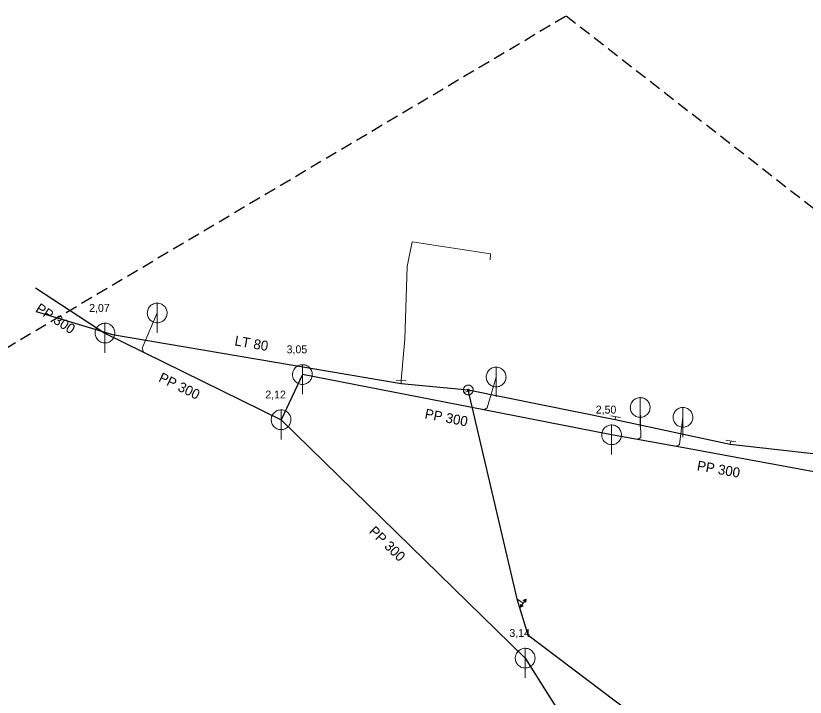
# Model space of a CAD drawing. Extents: x -683466 to -682479, y -996772 to -995963.
# Drawn here: x -683391.7 to -683311.7, y -996032.3 to -995963.2 of the extents above; entities that cross this region are included whole.
import ezdxf

# ---------------------------------------------------------------- set-up
doc = ezdxf.new("R2010")
doc.units = 0
doc.header["$LTSCALE"] = 0.4
doc.linetypes.add('MEDIUM_DASHED', pattern=[4.5, 3, -1.5])
doc.layers.add('1', color=7, linetype='Continuous')
for name, color, linetype, lineweight in [('11', 7, 'Continuous', 13), ('13', 7, 'Continuous', 13), ('14', 7, 'Continuous', 25), ('17', 7, 'Continuous', 25), ('22', 7, 'Continuous', 13), ('34', 7, 'Continuous', 13), ('47', 7, 'Continuous', 13), ('63', 7, 'MEDIUM_DASHED', 25)]:
    doc.layers.add(name, color=color, linetype=linetype, lineweight=lineweight)

msp = doc.modelspace()

# ---------------------------------------------------------------- linework, layer by layer
at = {"layer": '11'}
for points in [[(-683377.379, -995993.34), (-683378.896, -995996.921), (-683378.767, -995997.3)], [(-683343.05, -995999.829), (-683343.965, -996002.943), (-683344.296, -996003.166)], [(-683328.46, -996002.92), (-683328.388, -996005.949), (-683328.719, -996006.171)], [(-683324.129, -996003.91), (-683324.464, -996006.666), (-683324.795, -996006.888)]]:
    msp.add_lwpolyline(points, dxfattribs=at)
at = {"layer": '13'}
msp.add_lwpolyline([(-683352.66, -996000.18), (-683352.3, -995995.96), (-683352.059, -995988.629), (-683351.539, -995986.12), (-683343.629, -995987.34), (-683343.638, -995987.967)], dxfattribs=at)
at = {"layer": '14'}
for p, q in [((-683389.719, -995990.809), (-683382.67, -995995.379)), ((-683364.829, -996004.16), (-683340.109, -996028.32)), ((-683340.109, -996028.32), (-683325.27, -996051.789))]:
    msp.add_line(p, q, dxfattribs=at)
at = {"layer": '14', "lineweight": 13}
for p, q in [((-683352.66, -996000.18), (-683352.676, -996000.479)), ((-683345.871, -996001.145), (-683345.87, -996001.27)), ((-683330.998, -996004.133), (-683330.949, -996003.85)), ((-683319.329, -996006.62), (-683319.28, -996006.32))]:
    msp.add_line(p, q, dxfattribs=at)
at = {"layer": '14'}
for points in [[(-683382.67, -995995.379), (-683378.767, -995997.3), (-683364.829, -996004.16)], [(-683331.359, -996005.69), (-683344.296, -996003.166), (-683362.67, -995999.579), (-683364.829, -996004.16)], [(-683307.55, -996010.039), (-683324.795, -996006.888), (-683328.719, -996006.171), (-683331.359, -996005.69)]]:
    msp.add_lwpolyline(points, dxfattribs=at)
at = {"layer": '17'}
for points in [[(-683389.647, -995993.19), (-683381.916, -995995.522), (-683352.676, -996000.479), (-683345.871, -996001.145)], [(-683345.871, -996001.145), (-683330.998, -996004.133), (-683319.329, -996006.62), (-683296.567, -996009.217), (-683292.577, -996009.418), (-683277.891, -996009.01), (-683274.249, -996009.008), (-683238.954, -996008.579)], [(-683345.87, -996001.27), (-683340.96, -996022.3), (-683339.832, -996025.943), (-683304.056, -996053.017), (-683282.79, -996067.766), (-683274.905, -996069.189), (-683269.5, -996070.27), (-683248.91, -996070.167), (-683229.542, -996070.96), (-683219.888, -996069.96)]]:
    msp.add_lwpolyline(points, dxfattribs=at)
at = {"layer": '22'}
for p, q in [((-683377.379, -995995.34), (-683377.378, -995992.34)), ((-683382.67, -995997.379), (-683382.669, -995994.379)), ((-683362.67, -996001.579), (-683362.669, -995998.579)), ((-683343.05, -996001.829), (-683343.049, -995998.829)), ((-683328.46, -996004.92), (-683328.459, -996001.92)), ((-683364.829, -996006.16), (-683364.828, -996003.16)), ((-683324.129, -996005.91), (-683324.128, -996002.91)), ((-683331.359, -996007.69), (-683331.358, -996004.69)), ((-683340.109, -996030.32), (-683340.108, -996027.32))]:
    msp.add_line(p, q, dxfattribs=at)
for points in [[(-683376.379, -995993.34), (-683376.384, -995993.231), (-683376.402, -995993.123), (-683376.432, -995993.017), (-683376.472, -995992.916), (-683376.524, -995992.819), (-683376.586, -995992.729), (-683376.658, -995992.646), (-683376.738, -995992.572), (-683376.826, -995992.506), (-683376.92, -995992.451), (-683377.02, -995992.406), (-683377.125, -995992.373), (-683377.232, -995992.351), (-683377.341, -995992.341), (-683377.451, -995992.343), (-683377.559, -995992.357), (-683377.666, -995992.382), (-683377.769, -995992.419), (-683377.867, -995992.468), (-683377.959, -995992.526), (-683378.045, -995992.595), (-683378.122, -995992.672), (-683378.191, -995992.758), (-683378.25, -995992.85), (-683378.298, -995992.948), (-683378.335, -995993.051), (-683378.361, -995993.158), (-683378.375, -995993.266), (-683378.378, -995993.376), (-683378.368, -995993.485), (-683378.347, -995993.592), (-683378.313, -995993.696), (-683378.269, -995993.796), (-683378.214, -995993.891), (-683378.148, -995993.979), (-683378.074, -995994.059), (-683377.991, -995994.131), (-683377.901, -995994.193), (-683377.805, -995994.245), (-683377.703, -995994.286), (-683377.598, -995994.316), (-683377.49, -995994.334), (-683377.38, -995994.34), (-683377.271, -995994.334), (-683377.163, -995994.316), (-683377.058, -995994.287), (-683376.956, -995994.246), (-683376.859, -995994.194), (-683376.769, -995994.132), (-683376.686, -995994.061), (-683376.611, -995993.981), (-683376.546, -995993.893), (-683376.49, -995993.799), (-683376.446, -995993.699), (-683376.412, -995993.595), (-683376.39, -995993.487), (-683376.38, -995993.378)], [(-683381.67, -995995.379), (-683381.675, -995995.27), (-683381.693, -995995.162), (-683381.723, -995995.056), (-683381.763, -995994.955), (-683381.815, -995994.858), (-683381.877, -995994.768), (-683381.949, -995994.685), (-683382.029, -995994.611), (-683382.117, -995994.545), (-683382.211, -995994.49), (-683382.311, -995994.445), (-683382.416, -995994.412), (-683382.523, -995994.39), (-683382.632, -995994.38), (-683382.742, -995994.382), (-683382.85, -995994.396), (-683382.957, -995994.421), (-683383.06, -995994.458), (-683383.158, -995994.507), (-683383.25, -995994.565), (-683383.336, -995994.634), (-683383.413, -995994.711), (-683383.482, -995994.797), (-683383.541, -995994.889), (-683383.589, -995994.987), (-683383.626, -995995.09), (-683383.652, -995995.197), (-683383.666, -995995.305), (-683383.669, -995995.415), (-683383.659, -995995.524), (-683383.638, -995995.631), (-683383.604, -995995.735), (-683383.56, -995995.835), (-683383.505, -995995.93), (-683383.439, -995996.018), (-683383.365, -995996.098), (-683383.282, -995996.17), (-683383.192, -995996.232), (-683383.096, -995996.284), (-683382.994, -995996.325), (-683382.889, -995996.355), (-683382.781, -995996.373), (-683382.671, -995996.379), (-683382.562, -995996.373), (-683382.454, -995996.355), (-683382.349, -995996.326), (-683382.247, -995996.285), (-683382.15, -995996.233), (-683382.06, -995996.171), (-683381.977, -995996.1), (-683381.902, -995996.02), (-683381.837, -995995.932), (-683381.781, -995995.838), (-683381.737, -995995.738), (-683381.703, -995995.634), (-683381.681, -995995.526), (-683381.671, -995995.417)], [(-683361.67, -995999.579), (-683361.675, -995999.47), (-683361.693, -995999.362), (-683361.723, -995999.256), (-683361.763, -995999.155), (-683361.815, -995999.058), (-683361.877, -995998.968), (-683361.949, -995998.885), (-683362.029, -995998.811), (-683362.117, -995998.745), (-683362.211, -995998.69), (-683362.311, -995998.645), (-683362.416, -995998.612), (-683362.523, -995998.59), (-683362.632, -995998.58), (-683362.742, -995998.582), (-683362.85, -995998.596), (-683362.957, -995998.621), (-683363.06, -995998.658), (-683363.158, -995998.707), (-683363.25, -995998.765), (-683363.336, -995998.834), (-683363.413, -995998.911), (-683363.482, -995998.997), (-683363.541, -995999.089), (-683363.589, -995999.187), (-683363.626, -995999.29), (-683363.652, -995999.397), (-683363.666, -995999.505), (-683363.669, -995999.615), (-683363.659, -995999.724), (-683363.638, -995999.831), (-683363.604, -995999.935), (-683363.56, -996000.035), (-683363.505, -996000.13), (-683363.439, -996000.218), (-683363.365, -996000.298), (-683363.282, -996000.37), (-683363.192, -996000.432), (-683363.096, -996000.484), (-683362.994, -996000.525), (-683362.889, -996000.555), (-683362.781, -996000.573), (-683362.671, -996000.579), (-683362.562, -996000.573), (-683362.454, -996000.555), (-683362.349, -996000.526), (-683362.247, -996000.485), (-683362.15, -996000.433), (-683362.06, -996000.371), (-683361.977, -996000.3), (-683361.902, -996000.22), (-683361.837, -996000.132), (-683361.781, -996000.038), (-683361.737, -995999.938), (-683361.703, -995999.834), (-683361.681, -995999.726), (-683361.671, -995999.617)], [(-683342.05, -995999.829), (-683342.055, -995999.72), (-683342.073, -995999.612), (-683342.103, -995999.506), (-683342.143, -995999.405), (-683342.195, -995999.308), (-683342.257, -995999.218), (-683342.329, -995999.135), (-683342.409, -995999.061), (-683342.497, -995998.995), (-683342.591, -995998.94), (-683342.691, -995998.895), (-683342.796, -995998.862), (-683342.903, -995998.84), (-683343.012, -995998.83), (-683343.122, -995998.832), (-683343.23, -995998.846), (-683343.337, -995998.871), (-683343.44, -995998.908), (-683343.538, -995998.957), (-683343.63, -995999.015), (-683343.716, -995999.084), (-683343.793, -995999.161), (-683343.862, -995999.247), (-683343.921, -995999.339), (-683343.969, -995999.437), (-683344.006, -995999.54), (-683344.032, -995999.647), (-683344.046, -995999.755), (-683344.049, -995999.865), (-683344.039, -995999.974), (-683344.018, -996000.081), (-683343.984, -996000.185), (-683343.94, -996000.285), (-683343.885, -996000.38), (-683343.819, -996000.468), (-683343.745, -996000.548), (-683343.662, -996000.62), (-683343.572, -996000.682), (-683343.476, -996000.734), (-683343.374, -996000.775), (-683343.269, -996000.805), (-683343.161, -996000.823), (-683343.051, -996000.829), (-683342.942, -996000.823), (-683342.834, -996000.805), (-683342.729, -996000.776), (-683342.627, -996000.735), (-683342.53, -996000.683), (-683342.44, -996000.621), (-683342.357, -996000.55), (-683342.282, -996000.47), (-683342.217, -996000.382), (-683342.161, -996000.288), (-683342.117, -996000.188), (-683342.083, -996000.084), (-683342.061, -995999.976), (-683342.051, -995999.867)], [(-683327.46, -996002.92), (-683327.465, -996002.811), (-683327.483, -996002.703), (-683327.513, -996002.597), (-683327.553, -996002.496), (-683327.605, -996002.399), (-683327.667, -996002.309), (-683327.739, -996002.226), (-683327.819, -996002.152), (-683327.907, -996002.086), (-683328.001, -996002.031), (-683328.101, -996001.986), (-683328.206, -996001.953), (-683328.313, -996001.931), (-683328.422, -996001.921), (-683328.532, -996001.923), (-683328.64, -996001.937), (-683328.747, -996001.962), (-683328.85, -996001.999), (-683328.948, -996002.048), (-683329.04, -996002.106), (-683329.126, -996002.175), (-683329.203, -996002.252), (-683329.272, -996002.338), (-683329.331, -996002.43), (-683329.379, -996002.528), (-683329.416, -996002.631), (-683329.442, -996002.738), (-683329.456, -996002.846), (-683329.459, -996002.956), (-683329.449, -996003.065), (-683329.428, -996003.172), (-683329.394, -996003.276), (-683329.35, -996003.376), (-683329.295, -996003.471), (-683329.229, -996003.559), (-683329.155, -996003.639), (-683329.072, -996003.711), (-683328.982, -996003.773), (-683328.886, -996003.825), (-683328.784, -996003.866), (-683328.679, -996003.896), (-683328.571, -996003.914), (-683328.461, -996003.92), (-683328.352, -996003.914), (-683328.244, -996003.896), (-683328.139, -996003.867), (-683328.037, -996003.826), (-683327.94, -996003.774), (-683327.85, -996003.712), (-683327.767, -996003.641), (-683327.692, -996003.561), (-683327.627, -996003.473), (-683327.571, -996003.379), (-683327.527, -996003.279), (-683327.493, -996003.175), (-683327.471, -996003.067), (-683327.461, -996002.958)], [(-683363.829, -996004.16), (-683363.834, -996004.051), (-683363.852, -996003.943), (-683363.882, -996003.837), (-683363.922, -996003.736), (-683363.974, -996003.639), (-683364.036, -996003.549), (-683364.108, -996003.466), (-683364.188, -996003.392), (-683364.276, -996003.326), (-683364.37, -996003.271), (-683364.47, -996003.226), (-683364.575, -996003.193), (-683364.682, -996003.171), (-683364.791, -996003.161), (-683364.901, -996003.163), (-683365.009, -996003.177), (-683365.116, -996003.202), (-683365.219, -996003.239), (-683365.317, -996003.288), (-683365.409, -996003.346), (-683365.495, -996003.415), (-683365.572, -996003.492), (-683365.641, -996003.578), (-683365.7, -996003.67), (-683365.748, -996003.768), (-683365.785, -996003.871), (-683365.811, -996003.978), (-683365.825, -996004.086), (-683365.828, -996004.196), (-683365.818, -996004.305), (-683365.797, -996004.412), (-683365.763, -996004.516), (-683365.719, -996004.616), (-683365.664, -996004.711), (-683365.598, -996004.799), (-683365.524, -996004.879), (-683365.441, -996004.951), (-683365.351, -996005.013), (-683365.255, -996005.065), (-683365.153, -996005.106), (-683365.048, -996005.136), (-683364.94, -996005.154), (-683364.83, -996005.16), (-683364.721, -996005.154), (-683364.613, -996005.136), (-683364.508, -996005.107), (-683364.406, -996005.066), (-683364.309, -996005.014), (-683364.219, -996004.952), (-683364.136, -996004.881), (-683364.061, -996004.801), (-683363.996, -996004.713), (-683363.94, -996004.619), (-683363.896, -996004.519), (-683363.862, -996004.415), (-683363.84, -996004.307), (-683363.83, -996004.198)], [(-683323.129, -996003.91), (-683323.134, -996003.801), (-683323.152, -996003.693), (-683323.182, -996003.587), (-683323.222, -996003.486), (-683323.274, -996003.389), (-683323.336, -996003.299), (-683323.408, -996003.216), (-683323.488, -996003.142), (-683323.576, -996003.076), (-683323.67, -996003.021), (-683323.77, -996002.976), (-683323.875, -996002.943), (-683323.982, -996002.921), (-683324.091, -996002.911), (-683324.201, -996002.913), (-683324.309, -996002.927), (-683324.416, -996002.952), (-683324.519, -996002.989), (-683324.617, -996003.038), (-683324.709, -996003.096), (-683324.795, -996003.165), (-683324.872, -996003.242), (-683324.941, -996003.328), (-683325, -996003.42), (-683325.048, -996003.518), (-683325.085, -996003.621), (-683325.111, -996003.728), (-683325.125, -996003.836), (-683325.128, -996003.946), (-683325.118, -996004.055), (-683325.097, -996004.162), (-683325.063, -996004.266), (-683325.019, -996004.366), (-683324.964, -996004.461), (-683324.898, -996004.549), (-683324.824, -996004.629), (-683324.741, -996004.701), (-683324.651, -996004.763), (-683324.555, -996004.815), (-683324.453, -996004.856), (-683324.348, -996004.886), (-683324.24, -996004.904), (-683324.13, -996004.91), (-683324.021, -996004.904), (-683323.913, -996004.886), (-683323.808, -996004.857), (-683323.706, -996004.816), (-683323.609, -996004.764), (-683323.519, -996004.702), (-683323.436, -996004.631), (-683323.361, -996004.551), (-683323.296, -996004.463), (-683323.24, -996004.369), (-683323.196, -996004.269), (-683323.162, -996004.165), (-683323.14, -996004.057), (-683323.13, -996003.948)], [(-683330.359, -996005.69), (-683330.364, -996005.581), (-683330.382, -996005.473), (-683330.412, -996005.367), (-683330.452, -996005.266), (-683330.504, -996005.169), (-683330.566, -996005.079), (-683330.638, -996004.996), (-683330.718, -996004.922), (-683330.806, -996004.856), (-683330.9, -996004.801), (-683331, -996004.756), (-683331.105, -996004.723), (-683331.212, -996004.701), (-683331.321, -996004.691), (-683331.431, -996004.693), (-683331.539, -996004.707), (-683331.646, -996004.732), (-683331.749, -996004.769), (-683331.847, -996004.818), (-683331.939, -996004.876), (-683332.025, -996004.945), (-683332.102, -996005.022), (-683332.171, -996005.108), (-683332.23, -996005.2), (-683332.278, -996005.298), (-683332.315, -996005.401), (-683332.341, -996005.508), (-683332.355, -996005.616), (-683332.358, -996005.726), (-683332.348, -996005.835), (-683332.327, -996005.942), (-683332.293, -996006.046), (-683332.249, -996006.146), (-683332.194, -996006.241), (-683332.128, -996006.329), (-683332.054, -996006.409), (-683331.971, -996006.481), (-683331.881, -996006.543), (-683331.785, -996006.595), (-683331.683, -996006.636), (-683331.578, -996006.666), (-683331.47, -996006.684), (-683331.36, -996006.69), (-683331.251, -996006.684), (-683331.143, -996006.666), (-683331.038, -996006.637), (-683330.936, -996006.596), (-683330.839, -996006.544), (-683330.749, -996006.482), (-683330.666, -996006.411), (-683330.591, -996006.331), (-683330.526, -996006.243), (-683330.47, -996006.149), (-683330.426, -996006.049), (-683330.392, -996005.945), (-683330.37, -996005.837), (-683330.36, -996005.728)], [(-683339.109, -996028.32), (-683339.114, -996028.211), (-683339.132, -996028.103), (-683339.162, -996027.997), (-683339.202, -996027.896), (-683339.254, -996027.799), (-683339.316, -996027.709), (-683339.388, -996027.626), (-683339.468, -996027.552), (-683339.556, -996027.486), (-683339.65, -996027.431), (-683339.75, -996027.386), (-683339.855, -996027.353), (-683339.962, -996027.331), (-683340.071, -996027.321), (-683340.181, -996027.323), (-683340.289, -996027.337), (-683340.396, -996027.362), (-683340.499, -996027.399), (-683340.597, -996027.448), (-683340.689, -996027.506), (-683340.775, -996027.575), (-683340.852, -996027.652), (-683340.921, -996027.738), (-683340.98, -996027.83), (-683341.028, -996027.928), (-683341.065, -996028.031), (-683341.091, -996028.138), (-683341.105, -996028.246), (-683341.108, -996028.356), (-683341.098, -996028.465), (-683341.077, -996028.572), (-683341.043, -996028.676), (-683340.999, -996028.776), (-683340.944, -996028.871), (-683340.878, -996028.959), (-683340.804, -996029.039), (-683340.721, -996029.111), (-683340.631, -996029.173), (-683340.535, -996029.225), (-683340.433, -996029.266), (-683340.328, -996029.296), (-683340.22, -996029.314), (-683340.11, -996029.32), (-683340.001, -996029.314), (-683339.893, -996029.296), (-683339.788, -996029.267), (-683339.686, -996029.226), (-683339.589, -996029.174), (-683339.499, -996029.112), (-683339.416, -996029.041), (-683339.341, -996028.961), (-683339.276, -996028.873), (-683339.22, -996028.779), (-683339.176, -996028.679), (-683339.142, -996028.575), (-683339.12, -996028.467), (-683339.11, -996028.358)]]:
    msp.add_lwpolyline(points, close=True, dxfattribs=at)
at = {"layer": '34'}
for p, q in [((-683352.16, -996000.207), (-683353.159, -996000.151)), ((-683345.383, -996001.155), (-683346.357, -996001.383)), ((-683331.442, -996003.766), (-683330.456, -996003.934)), ((-683319.773, -996006.238), (-683318.786, -996006.402)), ((-683340.306, -996022.762), (-683340.959, -996022.3)), ((-683340.299, -996022.46), (-683340.02, -996022.356)), ((-683340.03, -996022.626), (-683340.272, -996022.451)), ((-683340.027, -996022.595), (-683340.244, -996022.438)), ((-683340.029, -996022.564), (-683340.214, -996022.43)), ((-683340.027, -996022.535), (-683340.187, -996022.42)), ((-683340.027, -996022.507), (-683340.161, -996022.409)), ((-683340.023, -996022.475), (-683340.132, -996022.397)), ((-683340.023, -996022.447), (-683340.105, -996022.388)), ((-683340.024, -996022.417), (-683340.075, -996022.38)), ((-683340.02, -996022.384), (-683340.046, -996022.366)), ((-683340.566, -996023.157), (-683340.592, -996023.139)), ((-683340.481, -996023.124), (-683340.591, -996023.047)), ((-683340.507, -996023.133), (-683340.591, -996023.075)), ((-683340.369, -996023.08), (-683340.59, -996022.928)), ((-683340.453, -996023.11), (-683340.589, -996023.015)), ((-683340.537, -996023.142), (-683340.589, -996023.106)), ((-683340.4, -996023.088), (-683340.588, -996022.959)), ((-683340.426, -996023.1), (-683340.588, -996022.988)), ((-683340.342, -996023.067), (-683340.587, -996022.897))]:
    msp.add_line(p, q, dxfattribs=at)
for points in [[(-683340.587, -996022.869), (-683340.592, -996023.167), (-683340.02, -996022.356)], [(-683340.02, -996022.356), (-683340.031, -996022.655), (-683340.299, -996022.46)], [(-683340.592, -996023.167), (-683340.315, -996023.056), (-683340.587, -996022.869)]]:
    msp.add_lwpolyline(points, dxfattribs=at)
at = {"layer": '47'}
for points in [[(-683345.371, -996001.145), (-683345.374, -996001.093), (-683345.382, -996001.041), (-683345.396, -996000.991), (-683345.414, -996000.942), (-683345.438, -996000.895), (-683345.467, -996000.851), (-683345.5, -996000.811), (-683345.537, -996000.774), (-683345.577, -996000.741), (-683345.621, -996000.712), (-683345.668, -996000.688), (-683345.717, -996000.67), (-683345.767, -996000.656), (-683345.819, -996000.648), (-683345.871, -996000.645), (-683345.923, -996000.648), (-683345.975, -996000.656), (-683346.026, -996000.67), (-683346.074, -996000.688), (-683346.121, -996000.712), (-683346.165, -996000.741), (-683346.206, -996000.774), (-683346.243, -996000.811), (-683346.276, -996000.851), (-683346.304, -996000.895), (-683346.328, -996000.942), (-683346.347, -996000.991), (-683346.36, -996001.041), (-683346.368, -996001.093), (-683346.371, -996001.145), (-683346.368, -996001.197), (-683346.36, -996001.249), (-683346.347, -996001.3), (-683346.328, -996001.348), (-683346.304, -996001.395), (-683346.276, -996001.439), (-683346.243, -996001.48), (-683346.206, -996001.517), (-683346.165, -996001.55), (-683346.121, -996001.578), (-683346.074, -996001.602), (-683346.026, -996001.621), (-683345.975, -996001.634), (-683345.923, -996001.642), (-683345.871, -996001.645), (-683345.819, -996001.642), (-683345.767, -996001.634), (-683345.717, -996001.621), (-683345.668, -996001.602), (-683345.621, -996001.578), (-683345.577, -996001.55), (-683345.537, -996001.517), (-683345.5, -996001.48), (-683345.467, -996001.439), (-683345.438, -996001.395), (-683345.414, -996001.348), (-683345.396, -996001.3), (-683345.382, -996001.249), (-683345.374, -996001.197)], [(-683345.789, -996001.145), (-683345.789, -996001.136), (-683345.791, -996001.128), (-683345.793, -996001.12), (-683345.796, -996001.112), (-683345.8, -996001.104), (-683345.805, -996001.097), (-683345.81, -996001.09), (-683345.816, -996001.084), (-683345.823, -996001.079), (-683345.83, -996001.074), (-683345.838, -996001.07), (-683345.846, -996001.067), (-683345.854, -996001.065), (-683345.862, -996001.063), (-683345.871, -996001.063), (-683345.88, -996001.063), (-683345.888, -996001.065), (-683345.896, -996001.067), (-683345.904, -996001.07), (-683345.912, -996001.074), (-683345.919, -996001.079), (-683345.926, -996001.084), (-683345.932, -996001.09), (-683345.938, -996001.097), (-683345.942, -996001.104), (-683345.946, -996001.112), (-683345.949, -996001.12), (-683345.951, -996001.128), (-683345.953, -996001.136), (-683345.953, -996001.145), (-683345.953, -996001.154), (-683345.951, -996001.162), (-683345.949, -996001.17), (-683345.946, -996001.178), (-683345.942, -996001.186), (-683345.938, -996001.193), (-683345.932, -996001.2), (-683345.926, -996001.206), (-683345.919, -996001.212), (-683345.912, -996001.216), (-683345.904, -996001.22), (-683345.896, -996001.223), (-683345.888, -996001.225), (-683345.88, -996001.227), (-683345.871, -996001.227), (-683345.862, -996001.227), (-683345.854, -996001.225), (-683345.846, -996001.223), (-683345.838, -996001.22), (-683345.83, -996001.216), (-683345.823, -996001.212), (-683345.816, -996001.206), (-683345.81, -996001.2), (-683345.805, -996001.193), (-683345.8, -996001.186), (-683345.796, -996001.178), (-683345.793, -996001.17), (-683345.791, -996001.162), (-683345.789, -996001.154)]]:
    msp.add_lwpolyline(points, close=True, dxfattribs=at)
at = {"layer": '63'}
msp.add_lwpolyline([(-683425.281, -996021.839), (-683425.281, -996016.256), (-683425.281, -996016.256), (-683335.962, -995963.223), (-683335.962, -995963.223), (-682479.059, -996630.324), (-682479.059, -996630.324), (-682551.631, -996711.269), (-682551.631, -996711.269), (-683416.907, -996083.246), (-683416.907, -996083.246)], close=True, dxfattribs=at)

# ---------------------------------------------------------------- texts
at = {"layer": '1'}
for s, rotation, p in [('PP 300', 327, (-683389.791, -995993.128)), ('LT 80 ', 350, (-683369.596, -995996.611)), ('PP 300', 334, (-683377.317, -996000.225)), ('PP 300', 349, (-683350.339, -996004.009)), ('PP 300', 350, (-683322.762, -996009.278)), ('PP 300', 316, (-683356.002, -996015.562))]:
    msp.add_text(s, height=1, rotation=rotation, dxfattribs=at).set_placement(p)
for s, p in [('2,07', (-683384.269, -995993.227)), ('3,05', (-683364.269, -995997.427)), ('2,12', (-683366.43, -996002.007)), ('2,50', (-683332.959, -996003.537)), ('3,14', (-683341.709, -996026.167))]:
    msp.add_text(s, height=0.8, dxfattribs=at).set_placement(p)

doc.saveas('drawing.dxf')
